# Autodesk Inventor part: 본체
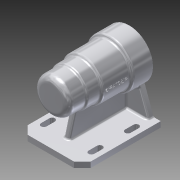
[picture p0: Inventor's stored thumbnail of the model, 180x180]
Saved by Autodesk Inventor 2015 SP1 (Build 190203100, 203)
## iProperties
Created: 2017-09
Part Number: 본체
Material: 알루미늄 6061
Document SubType Name: Modeling
Designer: C04
Density: 2.7 g/cm^3
Appearance: 알루미늄 - 평지
Mass: 701.586 g
Surface Area: 713.638 cm^2
Volume: 259.847 cm^3
Author: C04
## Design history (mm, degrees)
sketch "스케치1"
  geometry: L1 (-56, 0)-(56, 0); L2 (-56, 0)-(-56, 25); L3 (-56, 25)-(-31, 25); L4 (-31, 25)-(-31, 0); L5 (-31, 0)-(-31, 27); L6 (-31, 27)-(-11, 27); L7 (-11, 27)-(-11, 0); L8 (-11, 0)-(-11, 30); L9 (-11, 30)-(28, 30); L10 (28, 30)-(28, 0); L11 (28, 0)-(28, 34); L12 (28, 34)-(56, 34); L13 (56, 34)-(56, 0); 2 further points
  constraints: 26 end point, 7 perpendicular, 4 point on line, 3 vertical, 2 horizontal, 1 coincident, 1 midpoint
  dimensions: "d0" = 112 distance of L1.start L1.end; "d1" = 25 distance of L1.start L2.end; "d3" = 27 distance of L4.end L5.end; "d5" = 30 distance of L7.end L8.end; "d6" = 25 distance between parallel lines of L4 L2; "d7" = 45 distance between parallel lines of L7 L2; "d9" = 84 distance between parallel lines of L10 L2; "d10" = 34 distance of L10.end L11.end
revolve "회전1" sketch "스케치1" stored, may be unused: angle "d11" = 90 deg
sketch "스케치2"
  geometry: L1 (-56, -25)-(-56, 25) reference; L2 (-56, 0)-(56, 0); L3 (56, -34)-(56, 34) reference; L4 (56, 0)-(41, 0); L5 (41, 0)-(41, 21); L6 (41, 21)-(56, 21); L7 (41, 0)-(41, 24); L8 (41, 24)-(-13, 24); L9 (-13, 24)-(-13, 0); L10 (-13, 0)-(-13, 21); L11 (-13, 21)-(-25, 21); L12 (-25, 21)-(-25, 0); L13 (-25, 0)-(-25, 17.5); L14 (-25, 17.5)-(-43, 17.5); L15 (-43, 17.5)-(-43, 0); L16 (-43, 0)-(-43, 16); L17 (-43, 16)-(-47, 16); L18 (-47, 16)-(-47, 0); L19 (-47, 0)-(-47, 10.5); L20 (-47, 10.5)-(-50, 10.5); L21 (-50, 10.5)-(-50, 0); L22 (56, 21)-(56, 0); 1 further point
  constraints: 40 end point, 12 perpendicular, 12 point on line, 2 midpoint, 1 collinear
  dimensions: "d12" = 15 distance of L2.end L4.end; "d13" = 21 distance of L4.end L5.end; "d14" = 24 distance of L4.end L7.end; "d15" = 54 distance of L7.end L8.end; "d16" = 21 distance of L9.end L10.end; "d17" = 12 distance of L10.end L11.end; "d18" = 17.5 distance of L12.end L13.end; "d19" = 18 distance of L13.end L14.end; "d20" = 16 distance of L15.end L16.end; "d21" = 4 distance of L16.end L17.end; "d22" = 10.5 distance of L18.end L19.end; "d23" = 3 distance of L19.end L20.end
revolve "회전2" sketch "스케치2" stored, may be unused: angle "d25" = 90 deg
sketch "스케치3" dims "d26" = 52
  geometry: 3 further points
  constraints: 2 vertical alignment, 1 coincident, 2 other
hole "구멍1" sketch "스케치3" at (0, 26) diameter "d27" = 3.242; stored, may be unused: countersink angle "d31" = 90 deg, drill point angle "d33" = 118 deg; dims "d28" = 8, "d29" = 4, "d30" = 2, "d32" = 11
node "작업 평면1"
sketch "스케치4"
  geometry: L1 (-56, 45)-(56, 45); L2 (56, 45)-(56, -45); L3 (56, -45)-(-56, -45); L4 (-56, -45)-(-56, 45); L5 (56, -34)-(56, 34) reference; L6 (-56, 0)-(56, 0); L7 (-56, 34)-(56, 34); L8 (-56, -34)-(56, -34); L9 (32, 45)-(32, -45); L10 (20, 45)-(20, -45); L11 (-20, 45)-(-20, -45); L12 (-32, 45)-(-32, -45); L13 (-32, -34)-(-20, -34); L14 (-32, -38)-(-20, -38); L15 (-20, -30)-(-32, -30); L16 (20, -34)-(32, -34); L17 (20, -38)-(32, -38); L18 (32, -30)-(20, -30); L19 (20, 34)-(32, 34); L20 (28, 34)-(56, 34) reference; L21 (20, 30)-(32, 30); L22 (32, 38)-(20, 38); L23 (-32, 34)-(-20, 34); L24 (-32, 30)-(-20, 30); L25 (-20, 38)-(-32, 38); A1 r 4 centre (-32, -34) between (-32, -30) and (-32, -38); A2 r 4 centre (-20, -34) between (-20, -38) and (-20, -30); A3 r 4 centre (20, -34) between (20, -30) and (20, -38); A4 r 4 centre (32, -34) between (32, -38) and (32, -30); A5 r 4 centre (20, 34) between (20, 38) and (20, 30); A6 r 4 centre (32, 34) between (32, 30) and (32, 38); A7 r 4 centre (-32, 34) between (-32, 38) and (-32, 30); A8 r 4 centre (-20, 34) between (-20, 30) and (-20, 38); 8 further points
  constraints: 54 end point, 24 point on line, 16 point on circle, 16 tangent, 10 midpoint, 9 parallel, 8 centre point, 5 perpendicular, 2 vertical alignment, 1 horizontal, 1 vertical
  dimensions: "d38" = 90 distance of L1.end L2.end; "d39" = 112 distance of L1.start L1.end; "d42" = 34 distance of L6.start L7.start; "d43" = 34 distance of L8.start L6.start; "d44" = 11 distance between parallel lines of L1 L7; "d45" = 24 distance of L2.end L9.end; "d46" = 12 distance of L10.end L9.end; "d47" = 40 distance of L10.end L11.end; "d48" = 12 distance of L11.end L12.end; "d49" = 4 radius of A2; "d50" = 4 radius of A4; "d51" = 4 radius of A6; "d52" = 4 radius of A8
extrude "돌출1" join sketch "스케치4" distance "d53" = 8; taper "d54" = 0 deg
sketch "스케치5"
  geometry: L1 (0, 8)-(90, 8) reference; L2 (10, 8)-(24.57, 48.031); L3 (80, 8)-(65.43, 48.031); L4 (10, 8)-(80, 8); A1 r 30 centre (45, 70) between (24.57, 48.031) and (65.43, 48.031) reference; A2 r 30 centre (45, 70) between (24.57, 48.031) and (65.43, 48.031); 1 further point
  constraints: 6 end point, 4 point on circle, 2 point on line, 1 centre point, 1 coincident, 1 collinear
  dimensions: "d55" = 110 deg angle of L1 L2; "d56" = 110 deg angle of L1 L3; "d57" = 10 distance of L2.start L1.start; "d58" = 10 distance of L3.start L1.end
extrude "돌출2" join sketch "스케치5" distance "d59" = 8; taper "d60" = 0 deg
sketch "스케치6"
  geometry: L1 (56, -62)-(-56, -62) reference; L2 (-34, -62)-(-23.87, -24.193); L3 (56, -70)-(-56, -70) reference; L4 (-23.87, -24.193)-(-6.135, -26.657); L5 (-6.135, -26.657)-(32.198, -27.923); L6 (32.198, -27.923)-(50.642, -31.72); L7 (50.642, -31.72)-(50.642, -62); L8 (-34, -62)-(50.642, -62); 1 further point
  constraints: 12 end point, 2 point on line, 1 collinear, 1 perpendicular
  dimensions: "d62" = 22 horizontal distance of L2.start L3.end; "d63" = 105 deg angle of L1 L2; "d64" = 30.28018 distance of L6.end L7.end; "d65" = 18.44351 horizontal distance of L5.end L6.end; "d66" = 38.33356 horizontal distance of L4.end L5.end; "d67" = 17.73437 horizontal distance of L2.end L4.end; "d68" = 97.089 deg angle of L2 L4; "d69" = 170.258 deg angle of L6 L5; "d70" = 101.634 deg angle of L7 L6
extrude "돌출3" join sketch "스케치6" stored distance "d71" = 8; taper "d72" = 0 deg
chamfer "모따기1" distance "d73" = 12; stored, may be unused: second distance "d74" = 2, angle "d75" = 45 deg
fillet "모깎기1" dims "d76" = 9
fillet "모깎기2" dims "d77" = 3
fillet "모깎기3" dims "d78" = 3
chamfer "모따기2" distance "d79" = 1; stored, may be unused: second distance "d80" = 2, angle "d81" = 45 deg
fillet "모깎기4" dims "d82" = 0.3
node "작업 평면2"
sketch "스케치7"
  geometry: L1 (47.5, -26.008)-(47.5, 34) reference; 2 further points
  constraints: 1 horizontal alignment, 1 other
  dimensions: "d83" = 48 distance from line of L1 point (-0.5, 0)
feature "엠보싱1" sketch "스케치7" dims "d0" = 112, "d1" = 25, "d3" = 27, "d5" = 30, "d6" = 25, "d7" = 45, "d9" = 84, "d10" = 34, "d84" = 0.5, "d85" = 0
node "솔리드1"
pattern_circular "원형 패턴1" dims angle "d35" = 360 deg
